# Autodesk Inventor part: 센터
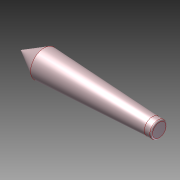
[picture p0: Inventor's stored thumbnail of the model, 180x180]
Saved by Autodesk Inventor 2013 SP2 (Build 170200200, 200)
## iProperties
Created: 2024-07
Part Number: 센터
Material: Generic
Document SubType Name: Modeling
Designer: 601
Density: 1 g/cm^3
Author: 601
변환 표준: STEP AP214IS
전처리기: Build: 200, Release: 2013 SP2 Update 6 - Date: Thu 07/17/2014
전송 단위: 밀리미터
불확실성: 0.01
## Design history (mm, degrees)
node "센터1"
node "솔리드1"
node "기준1"
